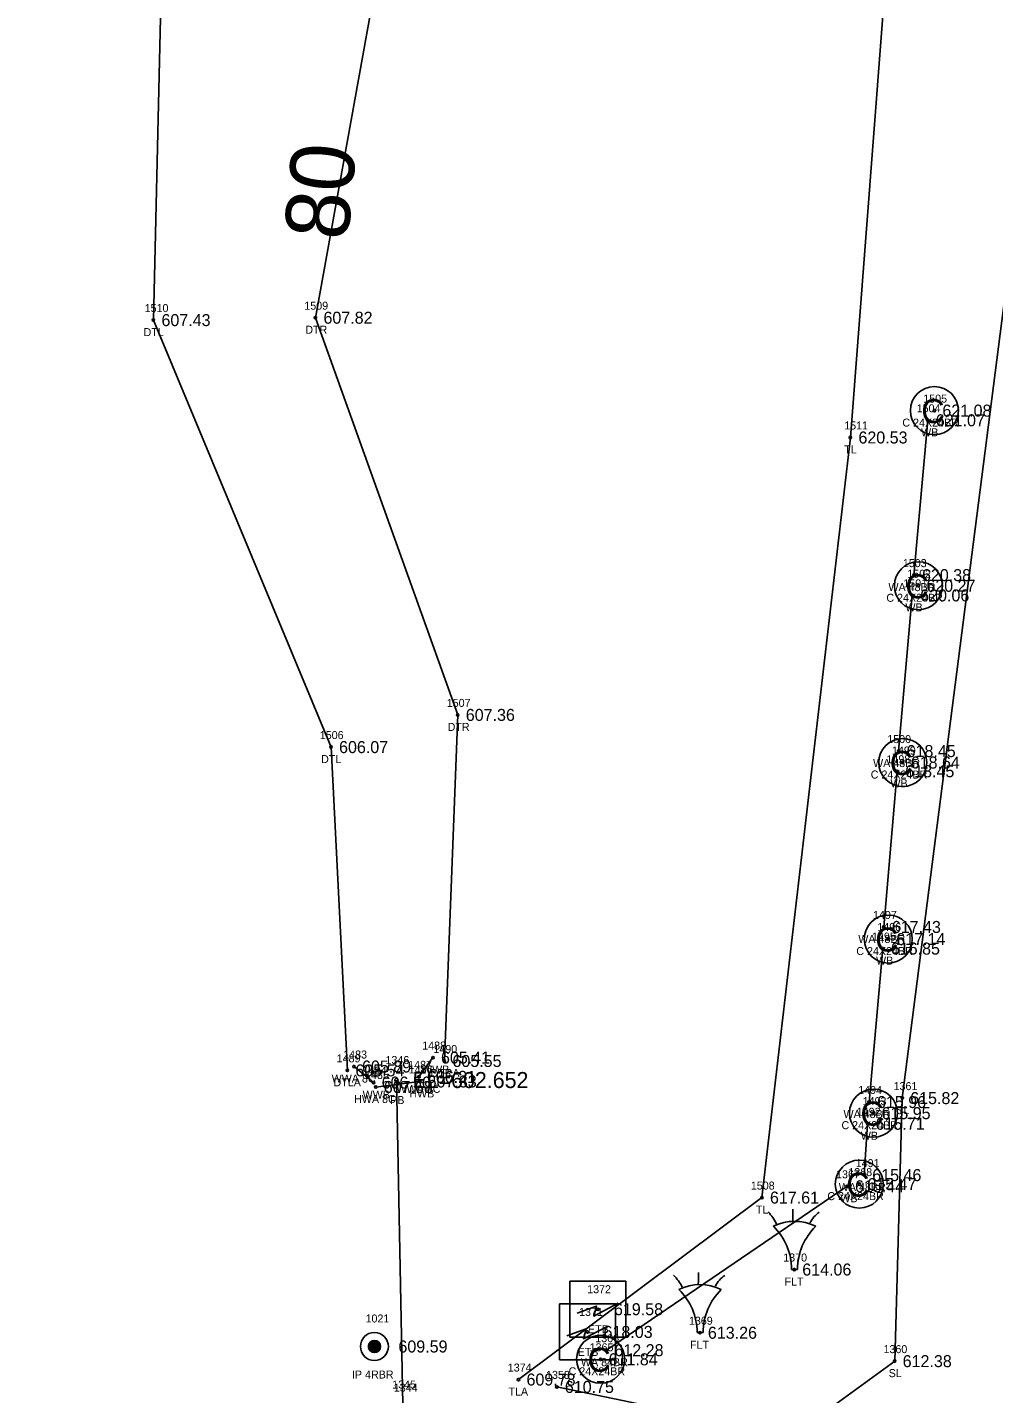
# Model space of a CAD drawing. Extents: x 1694813 to 1696862, y 1086485 to 1091027.
# Drawn here: x 1695696.3 to 1695817, y 1089981.5 to 1090152.3 of the extents above; entities that cross this region are included whole.
import ezdxf

# ---------------------------------------------------------------- set-up
doc = ezdxf.new("R2010")
doc.units = 0
for name, color, linetype in [('RD_EX_BldgApp', 7, 'Continuous'), ('RD_EX_BldgApp_txCode', 7, 'Continuous'), ('RD_EX_Bridge', 7, 'Continuous'), ('RD_EX_Bridge_txCode', 7, 'Continuous'), ('RD_EX_DR_Inlet_txCode', 7, 'Continuous'), ('RD_EX_DR_Pipe', 7, 'Continuous'), ('RD_EX_DR_Pipe_txCode', 7, 'Continuous'), ('RD_EX_DV_Prop_txCode', 7, 'Continuous'), ('RD_EX_DV_PropPin', 7, 'Continuous'), ('RD_EX_H2O', 7, 'Continuous'), ('RD_EX_H2O_txCode', 7, 'Continuous'), ('RD_EX_Misc_txCode', 7, 'Continuous'), ('RD_EX_TX_BldgApp_ELEV', 7, 'Continuous'), ('RD_EX_TX_Bridge_ELEV', 7, 'Continuous'), ('RD_EX_TX_DV_Prop_ELEV', 7, 'Continuous'), ('RD_EX_TX_H2O_ELEV', 7, 'Continuous'), ('RD_EX_TX_Misc_ELEV', 7, 'Continuous'), ('RD_EX_TX_UT_ELEV', 7, 'Continuous'), ('RD_EX_TX_VEG_ELEV', 7, 'Continuous'), ('RD_EX_UT', 7, 'Continuous'), ('RD_EX_UT_txCode', 7, 'Continuous'), ('RD_EX_VEG', 7, 'Continuous'), ('RD_EX_VEG_txCode', 7, 'Continuous'), ('RD_HC_TX_Sta50', 7, 'Continuous'), ('RD_SMD_Locator', 7, 'Continuous'), ('RD_TX_Pipe_ElevEX', 7, 'Continuous')]:
    doc.layers.add(name, color=color, linetype=linetype)

msp = doc.modelspace()

# ---------------------------------------------------------------- linework, layer by layer
at = {"layer": 'RD_EX_BldgApp'}
for p, q in [((1695807.08, 1090083.81), (1695808.81, 1090103.16)), ((1695805.16, 1090061.82), (1695806.86, 1090081.28)), ((1695803.31, 1090039.84), (1695804.99, 1090059.3)), ((1695801.46, 1090017.96), (1695803.19, 1090037.14)), ((1695800.87, 1090008.83), (1695801.28, 1090015.25)), ((1695768.64, 1089986.95), (1695798.71, 1090007.43)), ((1695791.78, 1089997.05), (1695792.53, 1089997.05)), ((1695779.97, 1089989.14), (1695780.72, 1089989.14))]:
    msp.add_line(p, q, dxfattribs=at)
for centre in [(1695809.63, 1090104.37), (1695807.63, 1090082.48), (1695805.68, 1090060.39), (1695803.87, 1090038.33), (1695802.02, 1090016.57), (1695800.25, 1090007.7), (1695767.91, 1089985.81)]:
    msp.add_circle(centre, 3, dxfattribs=at)
for centre, radius, start, end in [((1695785.46, 1090000.69), 4.89, 24.3279, 46.2665), ((1695792.15, 1089997.05), 6, 63.7794, 116.2206), ((1695754.07, 1090004.39), 37.88, 358.0671, 0.2715), ((1695797.04, 1090001.44), 3.28, 123.2906, 154.4886), ((1695784.28, 1089997.05), 7.5, 0, 45.8366), ((1695800.03, 1089997.05), 7.5, 134.1634, 180), ((1695773.65, 1089992.79), 4.89, 24.3279, 46.2665), ((1695742.26, 1089996.48), 37.88, 358.0671, 0.2715), ((1695785.23, 1089993.54), 3.28, 123.2906, 154.4886), ((1695780.34, 1089989.14), 6, 63.7794, 116.2206), ((1695772.47, 1089989.14), 7.5, 0, 45.8366), ((1695788.22, 1089989.14), 7.5, 134.1634, 180)]:
    msp.add_arc(centre, radius, start, end, dxfattribs=at)
at = {"layer": 'RD_EX_Bridge'}
for p, q in [((1695745.2, 1090021.11), (1695746.96, 1090023.52)), ((1695737.09, 1090022.4), (1695739.54, 1090020.39)), ((1695739.81, 1090019.84), (1695745.29, 1090020.53))]:
    msp.add_line(p, q, dxfattribs=at)
at = {"layer": 'RD_EX_DR_Pipe'}
msp.add_line((1695743.21, 1089980.16), (1695742.39, 1090020.71), dxfattribs=at)
at = {"layer": 'RD_EX_DV_PropPin'}
for p, q in [((1695738.94, 1089987.11), (1695738.94, 1089987.71)), ((1695738.97, 1089987.04), (1695738.97, 1089987.78)), ((1695739.01, 1089986.98), (1695739.01, 1089987.84)), ((1695739.04, 1089986.94), (1695739.04, 1089987.88)), ((1695739.08, 1089986.9), (1695739.08, 1089987.93)), ((1695739.11, 1089986.86), (1695739.11, 1089987.96)), ((1695739.15, 1089986.83), (1695739.15, 1089987.99)), ((1695739.18, 1089986.8), (1695739.18, 1089988.02)), ((1695739.22, 1089986.78), (1695739.22, 1089988.04)), ((1695739.25, 1089986.75), (1695739.25, 1089988.07)), ((1695739.29, 1089986.73), (1695739.29, 1089988.09)), ((1695739.32, 1089986.72), (1695739.32, 1089988.1)), ((1695739.36, 1089986.7), (1695739.36, 1089988.12)), ((1695739.39, 1089986.69), (1695739.39, 1089988.13)), ((1695739.43, 1089986.68), (1695739.43, 1089988.14)), ((1695739.46, 1089986.67), (1695739.46, 1089988.15)), ((1695739.5, 1089986.66), (1695739.5, 1089988.16)), ((1695739.53, 1089986.66), (1695739.53, 1089988.16)), ((1695739.57, 1089986.65), (1695739.57, 1089988.17)), ((1695739.6, 1089986.65), (1695739.6, 1089988.17)), ((1695739.64, 1089986.65), (1695739.64, 1089988.17)), ((1695739.67, 1089986.65), (1695739.67, 1089988.17)), ((1695739.71, 1089986.65), (1695739.71, 1089988.17)), ((1695739.74, 1089986.66), (1695739.74, 1089988.16)), ((1695739.78, 1089986.66), (1695739.78, 1089988.16)), ((1695739.81, 1089986.67), (1695739.81, 1089988.15)), ((1695739.85, 1089986.68), (1695739.85, 1089988.14)), ((1695739.88, 1089986.69), (1695739.88, 1089988.13)), ((1695739.92, 1089986.7), (1695739.92, 1089988.12)), ((1695739.95, 1089986.72), (1695739.95, 1089988.1)), ((1695739.99, 1089986.73), (1695739.99, 1089988.09)), ((1695740.02, 1089986.75), (1695740.02, 1089988.07)), ((1695740.06, 1089986.78), (1695740.06, 1089988.04)), ((1695740.09, 1089986.8), (1695740.09, 1089988.02)), ((1695740.13, 1089986.83), (1695740.13, 1089987.99)), ((1695740.16, 1089986.86), (1695740.16, 1089987.96)), ((1695740.2, 1089986.9), (1695740.2, 1089987.93)), ((1695740.23, 1089986.94), (1695740.23, 1089987.88)), ((1695740.27, 1089986.98), (1695740.27, 1089987.84)), ((1695740.3, 1089987.04), (1695740.3, 1089987.78)), ((1695740.34, 1089987.11), (1695740.34, 1089987.71)), ((1695738.9, 1089987.21), (1695738.9, 1089987.61)), ((1695740.37, 1089987.21), (1695740.37, 1089987.61))]:
    msp.add_line(p, q, dxfattribs=at)
for radius in [1.75, 0.761]:
    msp.add_circle((1695739.64, 1089987.41), radius, dxfattribs=at)
at = {"layer": 'RD_EX_H2O'}
for points in [[(1695748.39, 1090023.09), (1695750.06, 1090066.34), (1695732.27, 1090115.98), (1695751.04, 1090219.89), (1695755.24, 1090253.72), (1695734.04, 1090337.88), (1695767.29, 1090450.9), (1695816.74, 1090515.62), (1695823.85, 1090555.53), (1695842.49, 1090575.31), (1695858.41, 1090574.71), (1695872.4, 1090582.09)], [(1695736.26, 1090021.92), (1695734.22, 1090062.32), (1695712.02, 1090115.68), (1695713.59, 1090184.13), (1695696.25, 1090230.9)]]:
    msp.add_lwpolyline(points, dxfattribs=at)
at = {"layer": 'RD_EX_UT'}
for points in [[(1695764.08, 1089988.57), (1695764.08, 1089995.57), (1695771.08, 1089995.57), (1695771.08, 1089988.57)], [(1695762.78, 1089985.73), (1695762.78, 1089992.73), (1695769.78, 1089992.73), (1695769.78, 1089985.73)]]:
    msp.add_lwpolyline(points, close=True, dxfattribs=at)
for points in [[(1695764.97, 1089991.56), (1695767.4, 1089992.46), (1695767.05, 1089991.22), (1695770.1, 1089992.81)], [(1695763.68, 1089988.73), (1695766.1, 1089989.63), (1695765.76, 1089988.38), (1695768.8, 1089989.97)]]:
    msp.add_lwpolyline(points, dxfattribs=at)
at = {"layer": 'RD_EX_VEG'}
for points in [[(1695757.65, 1089983.28), (1695788.08, 1090006.02), (1695799.14, 1090101.01), (1695806.89, 1090202.11), (1695841.75, 1090315.15), (1695850.33, 1090414.2), (1695861.25, 1090510.87), (1695872.55, 1090614.26)], [(1695762.44, 1089982.36), (1695791.84, 1089976.26), (1695804.67, 1089985.58), (1695805.61, 1090018.45), (1695818.68, 1090120.45), (1695830.78, 1090219.77), (1695838.1, 1090274.39)]]:
    msp.add_lwpolyline(points, dxfattribs=at)
at = {"layer": 'RD_SMD_Locator'}
for centre, radius in [((1695712.02, 1090115.68), 0.15), ((1695732.27, 1090115.98), 0.15), ((1695809.63, 1090104.37), 0.15), ((1695808.81, 1090103.16), 0.15), ((1695799.14, 1090101.01), 0.15), ((1695807.08, 1090083.81), 0.15), ((1695807.63, 1090082.48), 0.15), ((1695806.86, 1090081.28), 0.15), ((1695750.06, 1090066.34), 0.15), ((1695734.22, 1090062.32), 0.15), ((1695805.16, 1090061.82), 0.15), ((1695804.99, 1090059.3), 0.15), ((1695805.68, 1090060.39), 0.15), ((1695803.31, 1090039.84), 0.15), ((1695803.19, 1090037.14), 0.15), ((1695803.87, 1090038.33), 0.15), ((1695746.96, 1090023.52), 0.15), ((1695736.26, 1090021.92), 0.15), ((1695737.09, 1090022.4), 0.15), ((1695748.39, 1090023.09), 0.15), ((1695739.54, 1090020.39), 0.15), ((1695742.39, 1090020.71), 0.2), ((1695745.2, 1090021.11), 0.15), ((1695745.29, 1090020.53), 0.15), ((1695739.81, 1090019.84), 0.15), ((1695805.61, 1090018.45), 0.15), ((1695801.46, 1090017.96), 0.15), ((1695802.02, 1090016.57), 0.15), ((1695801.28, 1090015.25), 0.15), ((1695800.87, 1090008.83), 0.15), ((1695798.71, 1090007.43), 0.15), ((1695800.25, 1090007.7), 0.15), ((1695788.08, 1090006.02), 0.15), ((1695792.12, 1089997.03), 0.15), ((1695767.58, 1089992.07), 0.15), ((1695766.28, 1089989.23), 0.15), ((1695780.32, 1089989.13), 0.15), ((1695739.64, 1089987.41), 0.15), ((1695767.91, 1089985.81), 0.15), ((1695768.64, 1089986.95), 0.15), ((1695804.67, 1089985.58), 0.15), ((1695757.65, 1089983.28), 0.15), ((1695762.44, 1089982.36), 0.15)]:
    msp.add_circle(centre, radius, dxfattribs=at)

# ---------------------------------------------------------------- texts
at = {"layer": 'RD_EX_BldgApp'}
for p in [(1695808, 1090102.81), (1695806, 1090080.91), (1695804.05, 1090058.83), (1695802.24, 1090036.77), (1695800.39, 1090015.01), (1695798.62, 1090006.14), (1695766.28, 1089984.25)]:
    msp.add_text('C', height=3, dxfattribs=at).set_placement(p)
at = {"layer": 'RD_EX_BldgApp_txCode'}
for s, p in [('1505', (1695808.24, 1090105.37)), ('C 24X24BR', (1695805.63, 1090102.37)), ('1502', (1695806.24, 1090083.48)), ('C 24X24BR', (1695803.63, 1090080.48)), ('1499', (1695804.33, 1090061.39)), ('C 24X24BR', (1695801.68, 1090058.39)), ('1496', (1695802.5, 1090039.33)), ('C 24X24BR', (1695799.87, 1090036.33)), ('1493', (1695800.67, 1090017.57)), ('C 24X24BR', (1695798.02, 1090014.57)), ('1368', (1695798.88, 1090008.7)), ('C 24X24BR', (1695796.25, 1090005.7)), ('1370', (1695790.74, 1089998.03)), ('FLT', (1695790.9, 1089995.03)), ('1369', (1695778.95, 1089990.13)), ('1365', (1695766.54, 1089986.81)), ('FLT', (1695779.09, 1089987.13)), ('C 24X24BR', (1695763.91, 1089983.81))]:
    msp.add_text(s, height=1, dxfattribs=at).set_placement(p)
at = {"layer": 'RD_EX_Bridge_txCode'}
for s, p in [('1488', (1695745.62, 1090024.52)), ('1483', (1695735.74, 1090023.4)), ('1484', (1695738.19, 1090021.39)), ('1485', (1695738.47, 1090020.84)), ('1487', (1695743.86, 1090022.11)), ('1486', (1695743.92, 1090021.53)), ('WWB', (1695745.59, 1090021.52)), ('WWA 8C', (1695734.29, 1090020.4)), ('WWA 8C', (1695742.4, 1090019.11)), ('HWA 8C', (1695737.1, 1090017.84)), ('WWB', (1695738.16, 1090018.39)), ('HWB', (1695744, 1090018.53))]:
    msp.add_text(s, height=1, dxfattribs=at).set_placement(p)
at = {"layer": 'RD_EX_DR_Inlet_txCode'}
msp.add_text('1344', height=1, dxfattribs=at).set_placement((1695742.06, 1089981.77))
at = {"layer": 'RD_EX_DR_Pipe_txCode'}
for s, p in [('1346', (1695741.02, 1090022.71)), ('PB', (1695741.61, 1090017.71)), ('1345', (1695741.86, 1089982.16))]:
    msp.add_text(s, height=1, dxfattribs=at).set_placement(p)
at = {"layer": 'RD_EX_DV_Prop_txCode'}
for s, p in [('1021', (1695738.53, 1089990.41)), ('IP 4RBR', (1695736.83, 1089983.41))]:
    msp.add_text(s, height=1, dxfattribs=at).set_placement(p)
at = {"layer": 'RD_EX_H2O_txCode'}
for s, p in [('1510', (1695710.92, 1090116.68)), ('1509', (1695730.88, 1090116.98)), ('DTL', (1695710.78, 1090113.68)), ('DTR', (1695731, 1090113.98)), ('1507', (1695748.68, 1090067.34)), ('DTR', (1695748.79, 1090064.34)), ('1506', (1695732.81, 1090063.32)), ('DTL', (1695732.97, 1090060.32)), ('1489', (1695734.92, 1090022.92)), ('1490', (1695747.01, 1090024.09)), ('DTRA', (1695746.64, 1090021.09)), ('DTLA', (1695734.53, 1090019.92))]:
    msp.add_text(s, height=1, dxfattribs=at).set_placement(p)
at = {"layer": 'RD_EX_Misc_txCode'}
for s, p in [('1504', (1695807.42, 1090104.16)), ('WB', (1695807.97, 1090101.16)), ('1503', (1695805.69, 1090084.81)), ('1501', (1695805.75, 1090082.28)), ('WA 48BR', (1695803.89, 1090081.81)), ('WB', (1695806.01, 1090079.28)), ('1500', (1695803.74, 1090062.82)), ('1498', (1695803.64, 1090060.3)), ('WA 48BR', (1695801.97, 1090059.82)), ('WB', (1695804.14, 1090057.3)), ('1497', (1695801.96, 1090040.84)), ('1495', (1695801.84, 1090038.14)), ('WA 48BR', (1695800.12, 1090037.84)), ('WB', (1695802.34, 1090035.14)), ('1494', (1695800.11, 1090018.96)), ('WA 48BR', (1695798.27, 1090015.96)), ('1492', (1695799.93, 1090016.25)), ('WB', (1695800.44, 1090013.25)), ('1491', (1695799.8, 1090009.83)), ('1367', (1695797.34, 1090008.43)), ('WA 48BR', (1695797.68, 1090006.83)), ('WB', (1695797.87, 1090005.43)), ('1366', (1695767.24, 1089987.95)), ('WA 84BR', (1695765.45, 1089984.95))]:
    msp.add_text(s, height=1, dxfattribs=at).set_placement(p)
at = {"layer": 'RD_EX_TX_BldgApp_ELEV'}
for s, p in [('621.08', (1695810.63, 1090103.62)), ('620.27', (1695808.63, 1090081.73)), ('618.64', (1695806.68, 1090059.64)), ('617.14', (1695804.87, 1090037.58)), ('615.95', (1695803.02, 1090015.82)), ('615.47', (1695801.25, 1090006.95)), ('614.06', (1695793.12, 1089996.28)), ('613.26', (1695781.32, 1089988.38)), ('611.84', (1695768.91, 1089985.06))]:
    msp.add_text(s, height=1.5, dxfattribs=at).set_placement(p)
at = {"layer": 'RD_EX_TX_Bridge_ELEV'}
for s, p in [('605.41', (1695747.96, 1090022.77)), ('605.89', (1695738.09, 1090021.65)), ('606.21', (1695746.2, 1090020.36)), ('606.56', (1695740.54, 1090019.64)), ('607.68', (1695740.81, 1090019.09)), ('607.33', (1695746.29, 1090019.78))]:
    msp.add_text(s, height=1.5, dxfattribs=at).set_placement(p)
at = {"layer": 'RD_EX_TX_DV_Prop_ELEV'}
msp.add_text('609.59', height=1.5, dxfattribs=at).set_placement((1695742.64, 1089986.66))
at = {"layer": 'RD_EX_TX_H2O_ELEV'}
for s, p in [('607.43', (1695713.02, 1090114.93)), ('607.82', (1695733.27, 1090115.23)), ('607.36', (1695751.06, 1090065.59)), ('606.07', (1695735.22, 1090061.57)), ('605.55', (1695749.39, 1090022.34)), ('605.54', (1695737.26, 1090021.17))]:
    msp.add_text(s, height=1.5, dxfattribs=at).set_placement(p)
at = {"layer": 'RD_EX_TX_Misc_ELEV'}
for s, p in [('621.07', (1695809.81, 1090102.41)), ('620.38', (1695808.08, 1090083.06)), ('620.06', (1695807.86, 1090080.53)), ('618.45', (1695806.16, 1090061.07)), ('618.45', (1695805.99, 1090058.55)), ('617.43', (1695804.31, 1090039.09)), ('616.85', (1695804.19, 1090036.39)), ('615.96', (1695802.46, 1090017.21)), ('615.71', (1695802.28, 1090014.5)), ('615.44', (1695799.71, 1090006.68)), ('615.46', (1695801.87, 1090008.08)), ('612.28', (1695769.64, 1089986.2))]:
    msp.add_text(s, height=1.5, dxfattribs=at).set_placement(p)
at = {"layer": 'RD_EX_TX_UT_ELEV'}
for s, p in [('619.58', (1695769.58, 1089991.32)), ('618.03', (1695768.28, 1089988.48))]:
    msp.add_text(s, height=1.5, dxfattribs=at).set_placement(p)
at = {"layer": 'RD_EX_TX_VEG_ELEV'}
for s, p in [('620.53', (1695800.14, 1090100.26)), ('615.82', (1695806.61, 1090017.7)), ('617.61', (1695789.08, 1090005.27)), ('612.38', (1695805.67, 1089984.83)), ('609.78', (1695758.65, 1089982.53)), ('610.75', (1695763.44, 1089981.61))]:
    msp.add_text(s, height=1.5, dxfattribs=at).set_placement(p)
at = {"layer": 'RD_EX_UT_txCode'}
for s, p in [('1372', (1695766.23, 1089994.07)), ('1371', (1695765.22, 1089991.23)), ('ETB', (1695766.33, 1089989.07)), ('ETB', (1695765.04, 1089986.23))]:
    msp.add_text(s, height=1, dxfattribs=at).set_placement(p)
at = {"layer": 'RD_EX_VEG_txCode'}
for s, p in [('1511', (1695798.36, 1090102.01)), ('TL', (1695798.36, 1090099.01)), ('1361', (1695804.53, 1090019.45)), ('SL', (1695804.86, 1090016.45)), ('1508', (1695786.69, 1090007.02)), ('TL', (1695787.31, 1090004.02)), ('1360', (1695803.27, 1089986.58)), ('1374', (1695756.31, 1089984.28)), ('1358', (1695761.09, 1089983.36)), ('SL', (1695803.92, 1089983.58)), ('TLA', (1695756.39, 1089981.28))]:
    msp.add_text(s, height=1, dxfattribs=at).set_placement(p)
at = {"layer": 'RD_HC_TX_Sta50'}
msp.add_text('80', height=8, rotation=84.8618, dxfattribs=at).set_placement((1695736.31, 1090125.52))
at = {"layer": 'RD_TX_Pipe_ElevEX'}
msp.add_text('EL=602.652', height=2, dxfattribs=at).set_placement((1695744.39, 1090019.71))

doc.saveas('drawing.dxf')
